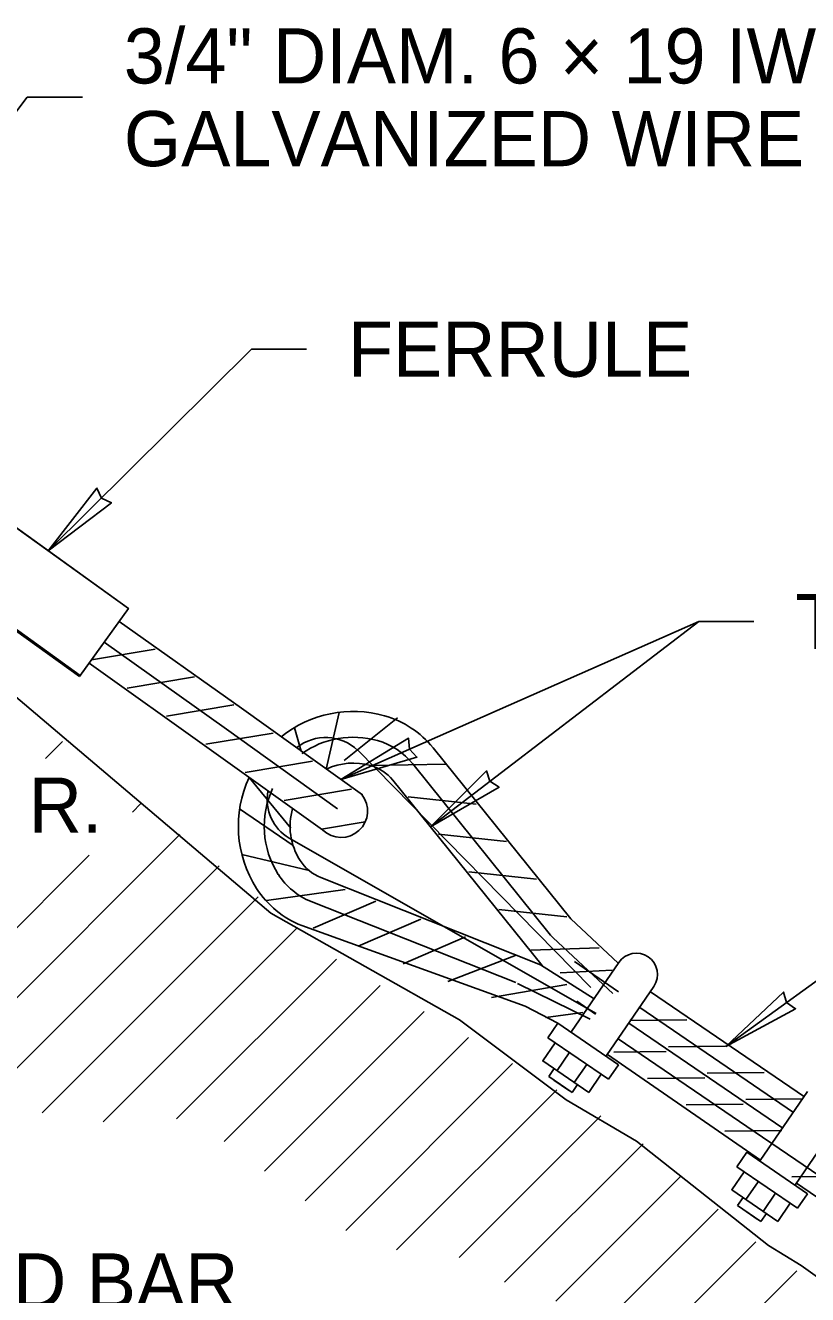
# Model space of a CAD drawing. Extents: x 99861 to 103151, y 100000 to 102076.
# Drawn here: x 100583.5 to 100810.3, y 100257.6 to 100625.9 of the extents above; entities that cross this region are included whole.
import ezdxf

# ---------------------------------------------------------------- set-up
doc = ezdxf.new("R2010")
doc.units = 0
for name, color, linetype in [('Level 1', 7, 'Continuous'), ('Level 10', 7, 'Continuous'), ('Level 15', 7, 'Continuous'), ('Level 2', 7, 'Continuous'), ('Level 20', 7, 'Continuous'), ('Level 28', 7, 'Continuous'), ('Level 4', 7, 'Continuous'), ('Level 6', 7, 'Continuous')]:
    doc.layers.add(name, color=color, linetype=linetype)

msp = doc.modelspace()

# ---------------------------------------------------------------- linework, layer by layer
at = {"layer": 'Level 1'}
for p, q in [((100701.68, 100416.26), (100741.64, 100366.59)), ((100689.99, 100406.86), (100733.37, 100353.06)), ((100681.19, 100402.58), (100681.04, 100402.72)), ((100669.71, 100392.36), (100669.63, 100392.43)), ((100669.13, 100378.62), (100732.9, 100353.25)), ((100663.6, 100364.68), (100728.43, 100341.27)), ((100741.64, 100366.59), (100755.35, 100353.82)), ((100732.9, 100353.25), (100748.44, 100343.46)), ((100764.79, 100345.42), (100809.42, 100314.97)), ((100728.43, 100341.27), (100737.88, 100336.35)), ((100758.52, 100336.39), (100803.15, 100305.93)), ((100807.1, 100289.92), (100852.57, 100258.89))]:
    msp.add_line(p, q, dxfattribs=at)
for points in [[(100681.19, 100402.58), (100646.11, 100427.71), (100610.66, 100452.95)], [(100669.63, 100392.43), (100637.4, 100415.52), (100601.91, 100440.79)], [(100796.69, 100296.61), (100752.32, 100327.3)]]:
    msp.add_lwpolyline(points, dxfattribs=at)
for centre, radius, start, end in [((100678.56, 100393.48), 33.34, 74.1665, 128.845), ((100680.1, 100398.9), 27.7, 38.8173, 74.1665), ((100678.56, 100393.48), 18.34, 74.1665, 115.2349), ((100680.1, 100398.9), 12.7, 38.8173, 74.1665), ((100678.56, 100393.48), 33.34, 154.8382, 212.6958), ((100675.02, 100397.93), 7.69, 226.375, 38.5322), ((100675.02, 100397.93), 7.69, 226.375, 38.5322), ((100678.56, 100393.48), 18.34, 163.6419, 212.6958), ((100673.82, 100390.43), 12.7, 212.6958, 248.367), ((100673.82, 100390.43), 27.7, 212.6958, 248.367)]:
    msp.add_arc(centre, radius, start, end, dxfattribs=at)
at = {"layer": 'Level 10'}
for p, q in [((100589.26, 100413.13), (100594.25, 100418.12)), ((100589.26, 100413.13), (100594.25, 100418.12)), ((100614.49, 100397.63), (100616.94, 100400.08)), ((100570.68, 100333.46), (100628.28, 100391.06)), ((100561.88, 100345.03), (100601.96, 100385.1)), ((100579.48, 100321.9), (100639.62, 100382.04)), ((100588.28, 100310.33), (100650.97, 100373.01)), ((100606.04, 100307.72), (100662.31, 100363.99)), ((100606.04, 100307.72), (100662.31, 100363.99)), ((100627.33, 100308.64), (100673.65, 100354.97)), ((100641.06, 100302.02), (100686.34, 100347.3)), ((100652.83, 100293.42), (100699.15, 100339.74)), ((100664.6, 100284.83), (100711.95, 100332.18)), ((100676.37, 100276.23), (100724.76, 100324.62)), ((100691.1, 100270.59), (100737.56, 100317.06)), ((100691.1, 100270.59), (100737.56, 100317.06)), ((100709.27, 100268.4), (100750.37, 100309.5)), ((100722.46, 100261.22), (100762.59, 100301.35)), ((100737.34, 100255.74), (100773.49, 100291.89)), ((100737.34, 100255.74), (100773.49, 100291.89)), ((100747.52, 100245.56), (100784.39, 100282.42)), ((100761.16, 100238.83), (100795.29, 100272.96)), ((100778.51, 100235.82), (100807.18, 100264.48)), ((100778.51, 100235.82), (100807.18, 100264.48))]:
    msp.add_line(p, q, dxfattribs=at)
at = {"layer": 'Level 15'}
for p, q in [((100584, 100605), (100512.76, 100511.1)), ((100584, 100605), (100600, 100605)), ((100590.1, 100473.39), (100649.01, 100531.89)), ((100665.01, 100531.89), (100649.01, 100531.89)), ((100674.92, 100407.07), (100778.74, 100452.9)), ((100700.91, 100393.33), (100778.74, 100452.9)), ((100778.74, 100452.9), (100794.74, 100452.9)), ((100876.45, 100394.66), (100786.62, 100329.56))]:
    msp.add_line(p, q, dxfattribs=at)
for points in [[(100590.1, 100473.39), (100604.19, 100491.6), (100605.55, 100488.73), (100608.4, 100487.36)], [(100674.92, 100407.07), (100697.01, 100413.56), (100694.84, 100415.86), (100694.6, 100419.02)], [(100700.91, 100393.33), (100720.85, 100404.83), (100718.2, 100406.56), (100717.22, 100409.57)], [(100786.62, 100329.56), (100806.86, 100340.54), (100804.25, 100342.33), (100803.35, 100345.37)]]:
    msp.add_lwpolyline(points, close=True, dxfattribs=at)
at = {"layer": 'Level 2'}
for p, q in [((100566.86, 100490.1), (100613.34, 100456.68)), ((100599.33, 100437.2), (100552.84, 100470.62)), ((100613.34, 100456.68), (100599.33, 100437.2))]:
    msp.add_line(p, q, dxfattribs=at)
msp.add_lwpolyline([(100549.91, 100457.1), (100654.66, 100368.29), (100709.41, 100337.34), (100740.32, 100314.17), (100760.67, 100302.17), (100798.98, 100271.91), (100808.43, 100266.08), (100871.82, 100220.81), (100988.21, 100150.42)], dxfattribs=at)
at = {"layer": 'Level 28'}
for p, q in [((100755.55, 100354), (100741.84, 100333.93)), ((100765.71, 100347.05), (100752, 100326.98)), ((100737.88, 100336.35), (100755.48, 100324.29)), ((100752.61, 100320.08), (100734.99, 100332.12)), ((100741.18, 100327.76), (100737.66, 100322.61)), ((100736.83, 100323.17), (100735.24, 100320.86)), ((100746.26, 100324.42), (100742.67, 100319.18)), ((100742.02, 100316.23), (100735.24, 100320.86)), ((100740.95, 100316.96), (100736.77, 100319.82)), ((100750.49, 100321.53), (100746.91, 100316.29)), ((100743.6, 100318.54), (100742.02, 100316.23)), ((100810.33, 100316.58), (100796.62, 100296.52)), ((100820.5, 100309.64), (100806.78, 100289.57)), ((100792.66, 100298.94), (100810.26, 100286.88)), ((100807.39, 100282.67), (100789.77, 100294.71)), ((100795.96, 100290.35), (100792.44, 100285.2)), ((100801.04, 100287.01), (100797.45, 100281.77)), ((100791.61, 100285.76), (100790.03, 100283.45)), ((100796.8, 100278.82), (100790.03, 100283.45)), ((100795.73, 100279.55), (100791.55, 100282.41)), ((100805.27, 100284.12), (100801.69, 100278.87)), ((100798.38, 100281.13), (100796.8, 100278.82))]:
    msp.add_line(p, q, dxfattribs=at)
for points in [[(100737.88, 100336.35), (100734.99, 100332.12)], [(100737.11, 100330.68), (100733.52, 100325.43), (100746.91, 100316.29)], [(100755.48, 100324.29), (100752.61, 100320.08)], [(100792.66, 100298.94), (100789.77, 100294.71)], [(100791.89, 100293.26), (100788.31, 100288.02), (100801.69, 100278.87)], [(100810.26, 100286.88), (100807.39, 100282.67)]]:
    msp.add_lwpolyline(points, dxfattribs=at)
msp.add_arc((100760.63, 100350.52), 6.15, 325.6477, 145.6477, dxfattribs=at)
at = {"layer": 'Level 4'}
for p, q in [((100602.65, 100441.82), (100621.1, 100444.92)), ((100602.65, 100441.82), (100621.1, 100444.92)), ((100612.98, 100433.52), (100632.51, 100436.8)), ((100612.98, 100433.52), (100632.51, 100436.8)), ((100624.39, 100425.4), (100643.91, 100428.68)), ((100624.39, 100425.4), (100643.91, 100428.68)), ((100674.46, 100426.46), (100670.74, 100410.06)), ((100691.39, 100424.93), (100675.9, 100412.6)), ((100635.78, 100417.29), (100655.31, 100420.52)), ((100635.78, 100417.29), (100655.31, 100420.52)), ((100663.43, 100415.26), (100661.54, 100422.08)), ((100747.5, 100346.67), (100679.89, 100415.53)), ((100647.16, 100409.14), (100666.7, 100412.37)), ((100705.42, 100411.55), (100683.56, 100411.12)), ((100695.84, 100411.56), (100735.8, 100361.89)), ((100660.41, 100392.98), (100648.38, 100407.65)), ((100658.54, 100400.99), (100678.08, 100404.22)), ((100714.17, 100399.94), (100694.49, 100402.07)), ((100661.14, 100387.89), (100645.55, 100398.51)), ((100669.3, 100392.67), (100682.04, 100394.77)), ((100659.99, 100390.04), (100749.01, 100339.2)), ((100722.95, 100389.03), (100703.26, 100391.16)), ((100665.74, 100380.63), (100646.25, 100385.26)), ((100731.72, 100378.12), (100712.04, 100380.26)), ((100676.19, 100375.13), (100653.38, 100371.95)), ((100666.37, 100371.65), (100725.66, 100348.14)), ((100685.12, 100371.75), (100666.95, 100363.89)), ((100740.5, 100367.22), (100720.81, 100369.35)), ((100698.14, 100366.58), (100679.96, 100358.73)), ((100711.15, 100361.42), (100692.98, 100353.57)), ((100735.8, 100361.89), (100736.53, 100361.11)), ((100736.53, 100361.11), (100753.83, 100344.99)), ((100725.76, 100356.09), (100705.99, 100348.41)), ((100749.88, 100358.23), (100730.09, 100357.53)), ((100755.46, 100345.43), (100742.75, 100354.26)), ((100753.62, 100351.77), (100738.55, 100350.98)), ((100740.51, 100347.58), (100718.63, 100343.84)), ((100726.23, 100347.89), (100747.23, 100337.48)), ((100745.17, 100339.42), (100734.42, 100338.04)), ((100761.66, 100340.9), (100806.29, 100310.45)), ((100758.77, 100337.12), (100775.33, 100337.32)), ((100758.77, 100337.12), (100775.33, 100337.32)), ((100755.39, 100331.87), (100797.21, 100303.33)), ((100769.27, 100328.14), (100754.15, 100327.96)), ((100769.98, 100329.47), (100786.54, 100329.67)), ((100769.98, 100329.47), (100786.54, 100329.67)), ((100780.48, 100320.49), (100763.92, 100320.29)), ((100781.19, 100321.82), (100797.75, 100322.02)), ((100781.19, 100321.82), (100797.75, 100322.02)), ((100791.69, 100312.84), (100775.13, 100312.64)), ((100792.4, 100314.18), (100808.96, 100314.38)), ((100792.4, 100314.18), (100808.96, 100314.38)), ((100802.9, 100305.19), (100786.34, 100304.99)), ((100797.21, 100303.33), (101017.69, 100152.88)), ((100822.3, 100291.96), (100805.74, 100291.76))]:
    msp.add_line(p, q, dxfattribs=at)
for points in [[(100674, 100398.53), (100641.76, 100421.62), (100606.29, 100446.88)], [(100748.77, 100338.97), (100743.36, 100342.72)]]:
    msp.add_lwpolyline(points, dxfattribs=at)
for centre, radius, start, end in [((100670.56, 100405.63), 13.6, 46.6543, 128.2039), ((100678.56, 100393.48), 25.84, 74.1665, 125.2847), ((100680.1, 100398.9), 20.2, 38.8173, 74.1665), ((100678.56, 100393.48), 25.84, 154.8382, 212.6958), ((100666.56, 100401.22), 12.97, 169.273, 239.4939), ((100673.82, 100390.43), 20.2, 212.6958, 248.367)]:
    msp.add_arc(centre, radius, start, end, dxfattribs=at)
at = {"layer": 'Level 6'}
msp.add_lwpolyline([(100599.12, 100436.91), (100613.34, 100456.68), (100566.86, 100490.1), (100552.64, 100470.34)], close=True, dxfattribs=at)

# ---------------------------------------------------------------- texts
at = {"layer": 'Level 20'}
for s, p in [('3/4" DIAM. 6 × 19 IWRC', (100612, 100609)), ('GALVANIZED WIRE ROPE', (100612, 100585)), ('THIMBLE', (100806.74, 100444.9)), ('10" MIN. R.', (100495.98, 100391.61)), ('HOLLOW CORE THREADED BAR', (100311.19, 100253.59))]:
    msp.add_text(s, height=16, dxfattribs=at).set_placement(p)
msp.add_text('FERRULE', height=16, rotation=360, dxfattribs=at).set_placement((100677.01, 100523.89))

doc.saveas('drawing.dxf')
